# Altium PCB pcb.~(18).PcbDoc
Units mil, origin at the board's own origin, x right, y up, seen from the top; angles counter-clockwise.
Board outline 2000 x 2390 mil, 2 copper layers (Top Layer, Bottom Layer); 15 components, 10 nets, 46 pads, 0 vias.
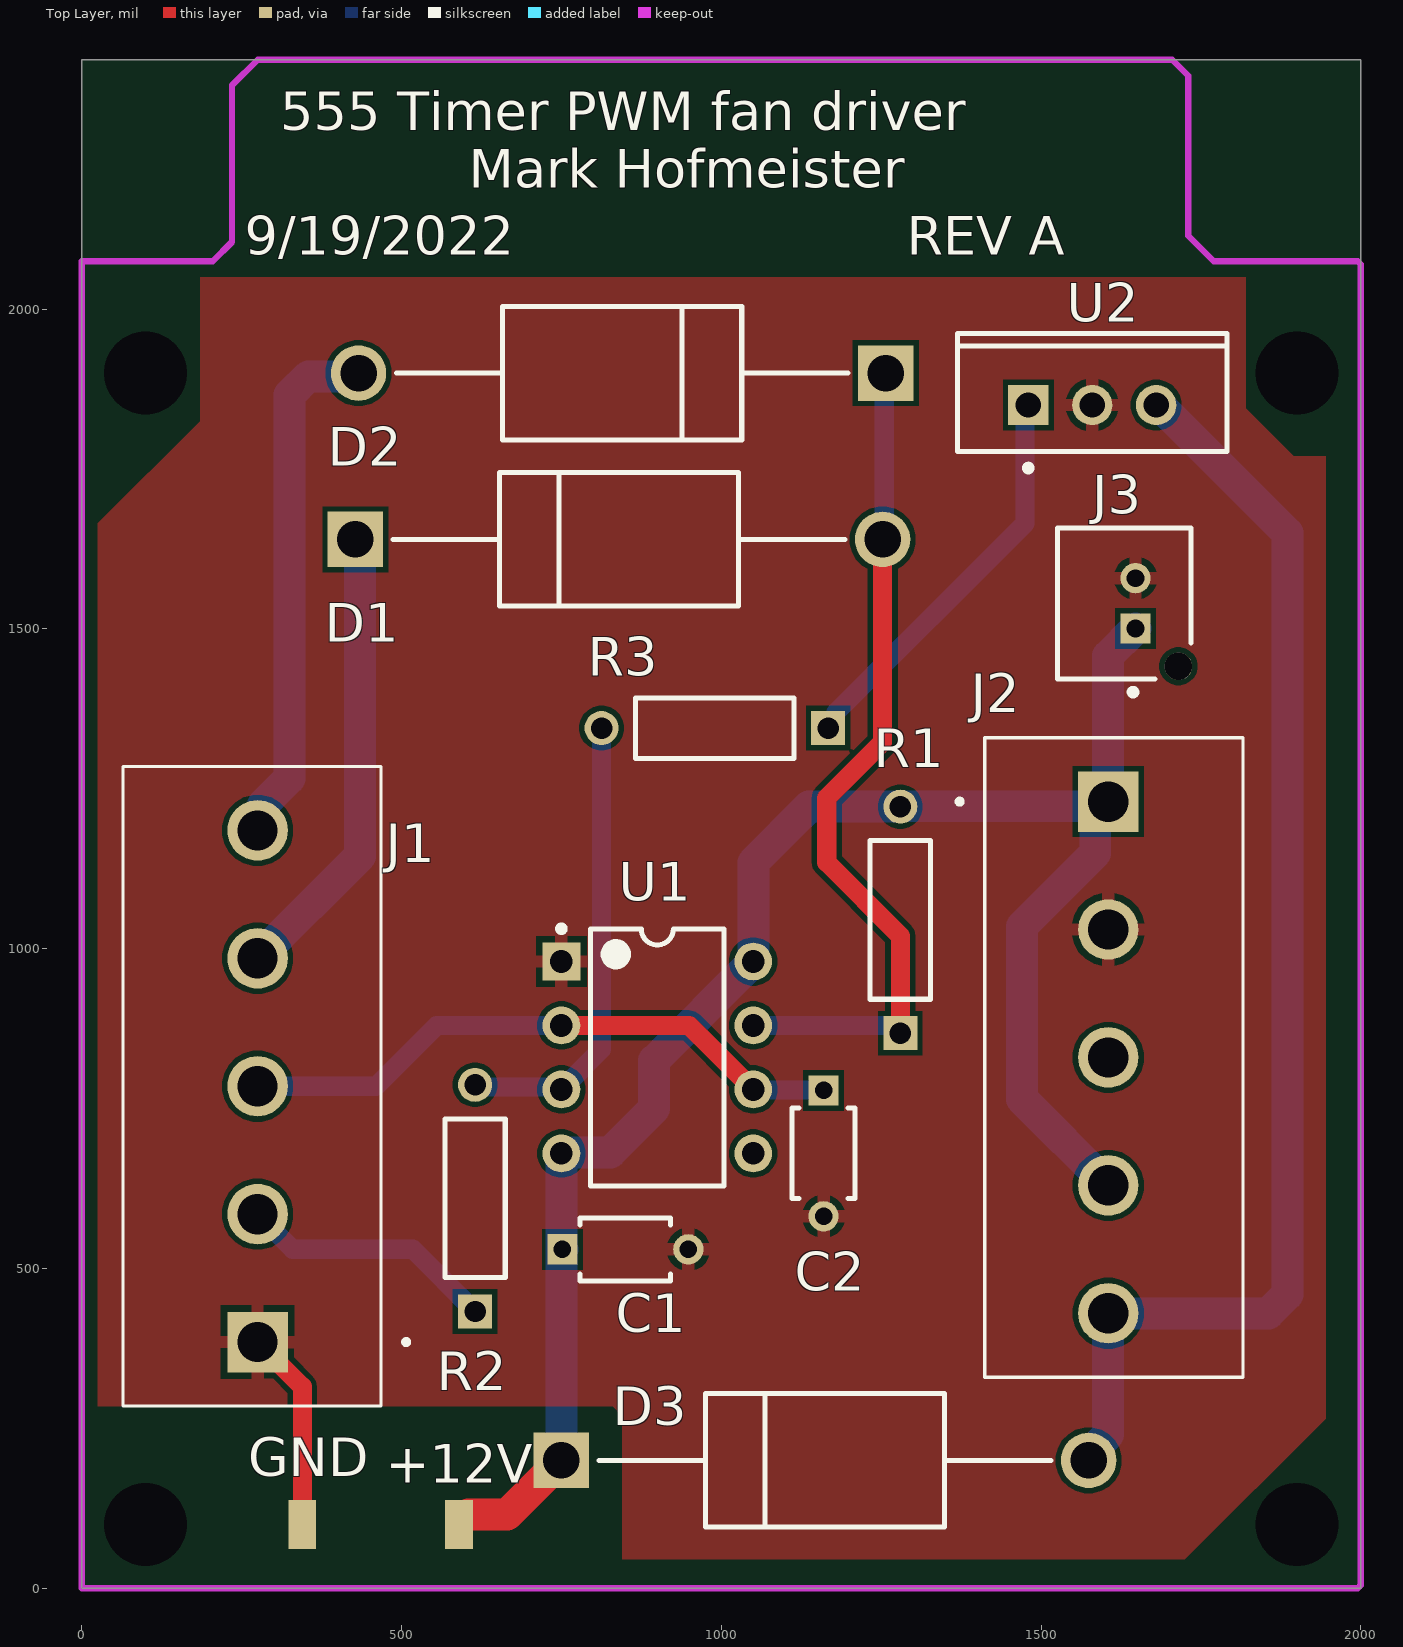
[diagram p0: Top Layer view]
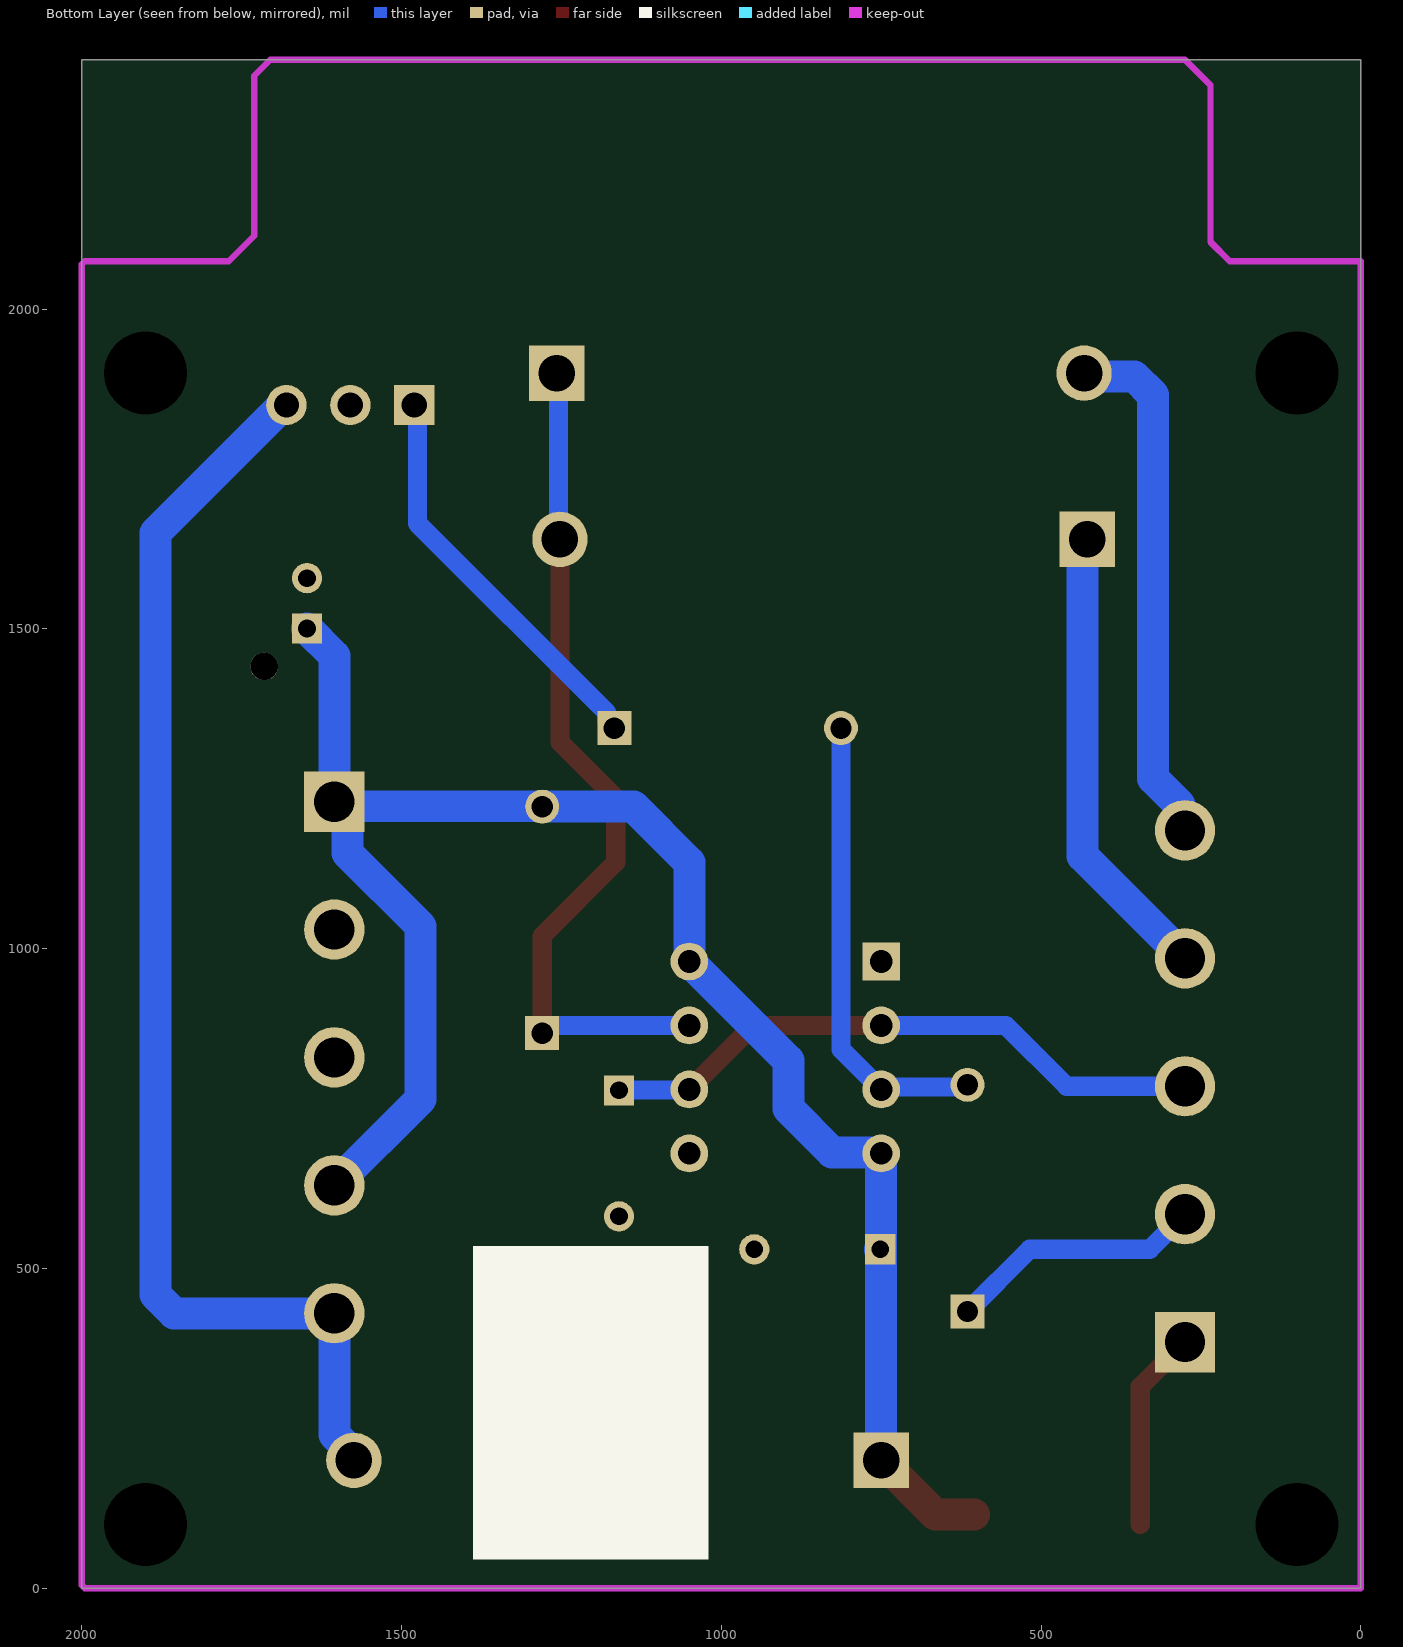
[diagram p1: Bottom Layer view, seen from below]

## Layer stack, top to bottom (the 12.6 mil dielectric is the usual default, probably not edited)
Top Solder: solder mask 0.4, Solder Resist, Dk 3.5
Top Layer: signal copper 1.4
Dielectric 1: dielectric 12.6, FR-4, Dk 4.8
Bottom Layer: signal copper 1.4
Bottom Solder: solder mask 0.4, Solder Resist, Dk 3.5

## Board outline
0,0 2000,0 2000,2390 0,2390

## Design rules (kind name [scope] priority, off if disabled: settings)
BoardOutlineClearance [All] p1: gap=7.87 ignorepadtopadclearanceinfootprint=FALSE except(15.75: Arc-SplitBarrior Arc-SplitContinuation Track-SplitBarrior Track-SplitContinuation SMDPad-SplitBarrior SMDPad-SplitContinuation THPad-SplitBarrior THPad-SplitContinuation Via-SplitBarrior Via-SplitContinuation Fill-SplitBarrior Fill-SplitContinuation Poly-SplitBarrior Poly-SplitContinuation Region-SplitBarrior Region-SplitContinuation Text-SplitBarrior Text-SplitContinuation)
Clearance "Clearance Bottom Layer" [OnLayer('Bottom Layer')] p1: gap=8 ignorepadtopadclearanceinfootprint=TRUE except(10: Arc-Text Track-Text SMDPad-Text THPad-Text Via-Text Fill-Text Poly-Text Region-Text Text-Text)
Clearance "Clearance Top Layer" [OnLayer('Top Layer')] p2: gap=8 ignorepadtopadclearanceinfootprint=TRUE except(10: Arc-Text Track-Text SMDPad-Text THPad-Text Via-Text Fill-Text Poly-Text Region-Text Text-Text)
Clearance [All] p3: gap=7.87 ignorepadtopadclearanceinfootprint=FALSE except(3.5: Arc-Arc Arc-Track Arc-SMDPad Track-Track Track-SMDPad SMDPad-SMDPad; 5: Arc-Via Track-Via SMDPad-Via THPad-Via Via-Via; 10: Arc-Text Track-Text SMDPad-Text THPad-Text Via-Text Fill-Text Poly-Text Region-Text Text-Text)
HoleSize [All] p1: absolutevalues=TRUE maxlimit=248.03 minlimit=7.87 maxpercent=80.000 minpercent=20.000
MinimumAnnularRing [All] p1: minimumring=3
MinimumSolderMaskSliver [All] p1: minsoldermaskwidth=3.94
PolygonConnect PolygonConnect_1 [All] p1: thpad.connectstyle=Relief thpad.reliefconductorwidth=20 thpad.reliefentries=4 thpad.polygonreliefangle="90 Angle" thpad.airgapwidth=10 smdpad.connectstyle=Relief smdpad.reliefconductorwidth=20 smdpad.reliefentries=4 smdpad.polygonreliefangle="90 Angle" smdpad.airgapwidth=10 via.connectstyle=Direct via.reliefconductorwidth=20 via.reliefentries=4 via.polygonreliefangle="90 Angle" via.airgapwidth=10
RoutingCorners [All] p1: cornerstyle=Round minsetback=100 maxsetback=100
RoutingVias [All] p1: holewidth=19.68 width=39.37 viastyle="Through Hole" minholewidth=7.87 minwidth=17.72 maxholewidth=39.37 maxwidth=78.74
SilkToSilkClearance [All] p1: silktosilkclearance=3.94
SilkToSolderMaskClearance [IsPad] p1: minsilkscreentomaskgap=3.94 clearancetoexposedcopper=TRUE
SolderMaskExpansion [All] p1: expansion=4 istentingtop=FALSE
Width [All] p1: maxlimit=100 minlimit=15 preferedwidth=30 minimp=50.000000 maximp=50.000000 favimp=50.000000
25 further rules are at their usual default settings.

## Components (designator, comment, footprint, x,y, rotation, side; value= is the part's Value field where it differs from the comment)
+12V "RCU-0C" TP+195X110 590,100 r90 top (schematic designator TP1)
C1 "RCER71H103K0K1H03B" FP-RCE0K1-MFG 850,530 r0 top
C2 "RCER71H103K0K1H03B" FP-RCE0K1-MFG 1160,680 r270 top
D1 "1N5408G-T" FP-DO-201AD-MFG 840,1640 r0 top
D2 "1N5408G-T" FP-DO-201AD-MFG 845,1900 r180 top
D3 "1N5408G-T" FP-DO-201AD-MFG 1162.2,200 r0 top
GND "RCU-0C" TP+195X110 345,100 r90 top (schematic designator TP2)
J1 "TB007-508-05BE" CUI_TB007-508-05BE 275,385 r90 top
J2 "TB007-508-05BE" CUI_TB007-508-05BE 1605,1230 r270 top
J3 "B02B-PASK-1(LF)(SN)" FP-B02B-PASK-1_LF_SN-MFG 1630,1540 r270 top
R1 "MFR-25FBF52-1K" RESA60-630X240 1280,1045 r90 top
R2 "MFR-25FBF52-1K" RESA60-630X240 615,610 r90 top
R3 "MFR-25FBF52-1K" RESA60-630X240 990,1345 r180 top
U1 "NE555P" P0008A 900,830 r0 top
U2 "LM395T/NOPB" NDE0003A 1580,1850 r0 top

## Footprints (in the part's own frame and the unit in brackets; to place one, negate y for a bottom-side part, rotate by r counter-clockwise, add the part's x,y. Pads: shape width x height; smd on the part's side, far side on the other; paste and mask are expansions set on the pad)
CUI_TB007-508-05BE [mm]
  rect 2.4x2.4 hole 1.6: 1(0,0)
  round 2.4 hole 1.6: 2(5.08,0) 3(10.16,0) 4(15.24,0) 5(20.32,0)
  silkscreen extent -2.54,-6 22.86,5.35
FP-B02B-PASK-1_LF_SN-MFG [mm]
  rect 1.2x1.2 hole 0.7 paste-1000 mask+0: 1(1,0.45)
  round 1.2 hole 0.7 paste-1000 mask+0: 2(-1,0.45)
  round 1.1 hole 1.1 unplated paste-1000 mask+0: ""(2.5,2.15)
  silkscreen extent -3,-2.65 3.65,2.65, body extent -3.1,-2.75 3.15,2.8, height 0.25
FP-DO-201AD-MFG [mm]
  rect 2.2x2.2 hole 1.45 paste-1000 mask+0: 1(-10.47,0)
  round 2.2 hole 1.45 paste-1000 mask+0: 2(10.47,0)
  silkscreen extent -8.97,-2.65 8.97,2.65, body extent -11.67,-2.75 11.67,2.75, height 0.25
FP-RCE0K1-MFG [mm]
  rect 1.2x1.2 hole 0.7 paste-1000 mask+0: 1(-2.5,0)
  round 1.2 hole 0.7 paste-1000 mask+0: 2(2.5,0)
  silkscreen extent -1.8,-1.25 1.8,1.25, body extent -3.2,-1.35 3.2,1.35, height 0.25
NDE0003A [mm] "FM, 3-Leads, Body 10.7x4.7mm, Pitch 2.54mm"
  rect 1.6x1.6 hole 1: 1(-2.54,0)
  round 1.6 hole 1: 2(0,0) 3(2.54,0)
  silkscreen extent -5.35,-2.62 5.35,2.85, body extent -5.4,-1.9 5.4,2.9, height 19.4
P0008A [mm] "DIP, 8-Leads, Body 10.15x6.6mm, Pitch 2.54mm"
  rect 1.5x1.5 hole 0.9: 1(-3.81,3.81)
  round 1.5 hole 0.9: 2(-3.81,1.27) 3(-3.81,-1.27) 4(-3.81,-3.81) 5(3.81,-3.81) 6(3.81,-1.27) 7(3.81,1.27) 8(3.81,3.81)
  silkscreen extent -3.93,-5.1 2.65,5.23, body extent -3.95,-5.07 3.95,5.07, height 5.08
RESA60-630X240 [mm] "Axial Resistor, 2-Leads, Dia 2.4mm, Body Length 6.3mm"
  rect 1.35x1.35 hole 0.85: 1(-4.5,0)
  round 1.35 hole 0.85: 2(4.5,0)
  silkscreen extent -3.15,-1.2 3.15,1.2, body extent -3.15,-1.2 3.15,1.2, height 2.4
TP+195X110 [mm]
  rect 1.95x1.1 smd: 1(0,0)
  body extent -0.8,-0.45 0.8,0.45, height 1.3

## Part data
+12V GND: "Natural PC Test Point - - Plating Surface Mount Mounting Type", Package=None
C1 C2: library part CMP-06035-044411-1, "Cap Ceramic 10nF 50V X7R ±10% Radial 5mm +125°C Automotive Bulk", Capacitance=10nF, Case/Package=Radial, Dielectric=X7R, Max Operating Temperature=125°C, Min Operating Temperature=-55°C, Package Quantity=500, Ratings=AEC-Q200, Resistor Type=Ceramic, Tolerance=10%, Voltage Rating=50V
D1 D2 D3: library part CMP-12791-000058-1, "DIODE GEN PURP 1KV 3A DO201AD", Average Rectified Current=3A, Capacitance=40pF, Case/Package=DO-201AD, Forward Voltage=1.1V, Max Operating Temperature=150°C, Max Repetitive Reverse Voltage (Vrrm)=1kV, Max Reverse Current=5uA, Max Surge Current=125A, Min Operating Temperature=-65°C, Package Quantity=1200
J1 J2: Package=None
J3: library part CMP-17439-000415-1, "CONN HEADER VERT 2POS 2MM", Color=Natural, Current Rating=3A, Flammability Rating="UL94 V-0", Housing Color=White, Insulation Resistance=1GR, Max Operating Temperature=85°C, Min Operating Temperature=-25°C, Voltage Rating=250V
R1 R2 R3: library part CMP-1659-00075-1, "Axial Resistor, 1 KOhm, +/- 1%, 250 mW, -55 to 155 degC, 2-Pin THD, RoHS, Bulk", Case\Package=Axial, Max Operating Temperature="155 degC", Min Operating Temperature="-55 degC", Package Quantity=200, Power Rating="250 mW", Resistance="10 kohm", Tolerance=1%, Voltage Rating="250 V"
U1: library part CMP-2000-04954-1, "Precision Timer, 4.5 to 16 V, 0 to 70 degC, 8-Pin DIP, Pb-Free, Tube", Manufacturer=TexasInstruments, Maximum High Level Output Current=-200mA, Maximum Low Level Output Current=200mA, Operating Supply Voltage=5, Package=8PDIP, Package Description="8-Pin Double In-line Package, Body 9.59 x 6.35 mm, Pitch 2.54 mm", Package Reference=P8
U2: library part CMP-0063-01416-3, "Ultra Reliable Power Transistor, 3-pin TO-220, Pb-Free", Manufacturer="Texas Instruments", PackageTopMarking=NSUZXYTTE#*LM395T, PowerWise=N

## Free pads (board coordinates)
  round 60 hole 130: 4(1900,1900) 5(1900,100) 6(100,100) 7(100,1900)

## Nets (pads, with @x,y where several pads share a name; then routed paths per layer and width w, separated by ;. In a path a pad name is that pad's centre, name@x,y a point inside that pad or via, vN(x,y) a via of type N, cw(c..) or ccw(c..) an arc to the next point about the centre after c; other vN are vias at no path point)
GND: C1.2 C2.2 GND.1 J1.1 J2.2 J3.2 U1.1 U2.2 | length 314
  Top Layer w30: J1.1 345,315 GND.1
LED_IN: J1.2 R2.1 | length 403
  Bottom Layer w30: J1.2 330,530 517.83,530 R2.1
NetC2_1: C2.1 J1.3 U1.2 U1.6 | length 966.4
  Top Layer w30: U1.2 950,880 U1.6
  Bottom Layer w30: J1.3 460,785 555,880 U1.2 ; U1.6 1050.79,779.21 1159.21,779.21 C2.1
NetD1_1: D1.1 J1.4 | length 724.3
  Bottom Layer w50: J1.4 435,1145 435,1632.8 D1.1
NetD1_2: D1.2 D2.1 R1.1 U1.7 | length 1353
  Top Layer w30: D1.2 1252.2,1322.8 1165,1235.59 1165,1135 1280,1020 R1.1
  Bottom Layer w30: U1.7 1267.83,880 R1.1 ; D1.2 1254.7,1642.5 1254.7,1897.5 D2.1
NetD2_2: D2.2 J1.5 | length 811.3
  Bottom Layer w50: J1.5 283.51,1193.51 283.51,1224.97 325,1266.46 325,1865.71 354.29,1895 D2.2@422.8,1895
NetD3_2: D3.2 J2.5 U2.3 | length 2013.6
  Bottom Layer w50: D3.2 1574.41,209.91 1605,240.5 J2.5 1855.71,430 1885,459.29 1885,1650 1691.5,1843.5 1690.01,1843.5 U2.3@1680.82,1852.69
NetR2_2: R2.2 R3.2 U1.3 | length 729.5
  Bottom Layer w30: R2.2@615.33,787.5 R2.2 618.58,783.58 746.42,783.58 U1.3 812.83,842.83 R3.2
NetR3_1: R3.1 U2.1 | length 634.6
  Bottom Layer w30: R3.1 1178.74,1356.57 1178.74,1368.74 1475,1665 1475,1845 U2.1
VCC: +12V.1 C1.1 D3.1 J2.1 J2.4 J3.1 R1.2 U1.4 U1.8 | length 2869
  Top Layer w50: +12V.1@605,115 665,115 D3.1
  Bottom Layer w50: D3.1 750,528.43 C1.1 750,531.57 U1.4 751.73,681.73 826.73,681.73 895,750 895,825 U1.8 1050,1135 1137.17,1222.17 R1.2 1280.6,1222.77 J2.1@1597.77,1222.77 ; J2.4 1470,765 1470,1035 1584.72,1149.72 1584.72,1209.72 J2.1@1597.77,1222.77 ; J3.1 1605,1457.91 J2.1 J2.1@1597.77,1222.77
pads on no net: J2.3 J3. U1.5

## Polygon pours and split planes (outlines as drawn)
GND on Top Layer "GND_L01_P000" (solid, pour order 0): 1820,2050 1820,1845 1895,1770 1945,1770 1945,265 1725,45 845,45 845,270 830,285 25,285 25,1665 185,1825 185,2050 195,2050

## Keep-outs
Keep-Out Layer:
  lines w10: 0,0 1995,0 2000,5 2000,2070 1995,2075 1770,2075 1730,2115 1730,2365 1705,2390 275,2390 235,2350 235,2105 205,2075 0,2075 0,0

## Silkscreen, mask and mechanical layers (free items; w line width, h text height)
Top Overlay:
  text "555 Timer PWM fan driver" at 310.22,2280 h60
  text "Mark Hofmeister" at 605,2190 h60
  text "9/19/2022" at 255,2085 h60
  text "REV A" at 1290,2085 h60
Bottom Overlay:
  region: 1129.59,535 1387.5,535 1387.5,45 1020,45 1020,535 1129.44,535
  text "The real circuit that you're working on is a circuit called yourself. The board that appears to be \"out there\" and the engineer that appears to be \"in here\" are not two separate things. They grow towards Quality or fall away from Quality together." at 1622.29,1955 h30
